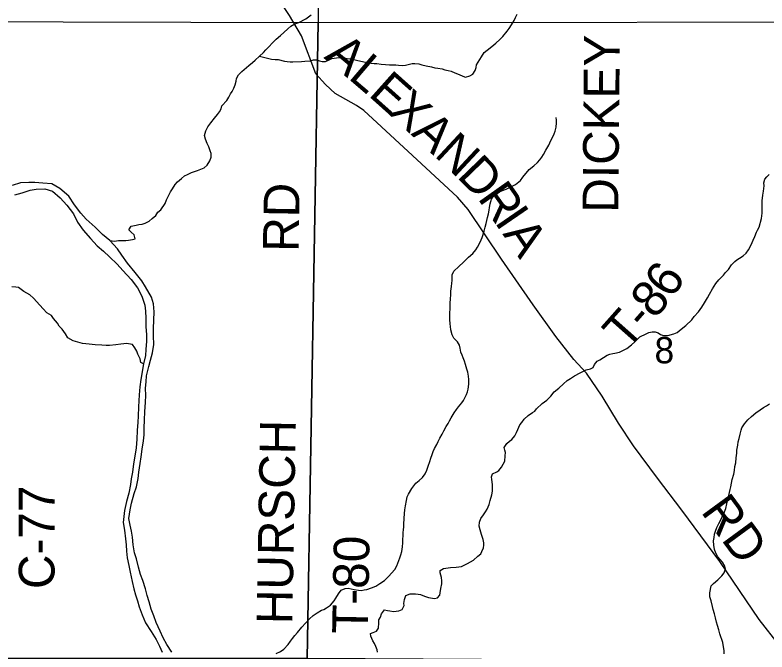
# Model space of a CAD drawing. Extents: x 0 to 34, y 0 to 22.
# Drawn here: x 2.685 to 3.881, y 19.157 to 20.171 of the extents above; entities that cross this region are included whole.
import ezdxf

# ---------------------------------------------------------------- set-up
doc = ezdxf.new("R2010")
doc.units = 0
for name, color, linetype in [('GM_X_Corporation', 7, 'Continuous'), ('GM_X_County_Road', 7, 'Continuous'), ('GM_X_County_Road_Text', 7, 'Continuous'), ('GM_X_Minor_River', 7, 'Continuous'), ('GM_X_Section_Text', 7, 'Continuous'), ('GM_X_Township_Road_Text', 7, 'Continuous')]:
    doc.layers.add(name, color=color, linetype=linetype)

msp = doc.modelspace()

# ---------------------------------------------------------------- linework, layer by layer
at = {"layer": 'GM_X_Corporation'}
for points in [[(4.1833, 20.898), (3.1749, 20.898), (3.1676, 20.1592), (4.1816, 20.1598)], [(3.1676, 20.1592), (3.1497, 19.1471), (2.1459, 19.1467), (2.1533, 20.1617)], [(3.1676, 20.1592), (4.1816, 20.1598), (4.1654, 19.1412), (3.1497, 19.1471)]]:
    msp.add_lwpolyline(points, close=True, dxfattribs=at)
at = {"layer": 'GM_X_County_Road'}
msp.add_lwpolyline([(3.901, 19.1674), (3.8689, 19.2091), (3.8059, 19.3011), (3.7455, 19.3827), (3.7071, 19.4339), (3.6691, 19.4851), (3.6451, 19.5215), (3.6192, 19.5642), (3.594, 19.6011), (3.5739, 19.6226), (3.5452, 19.6595), (3.5095, 19.7098), (3.4591, 19.7826), (3.4058, 19.8616), (3.389, 19.881), (3.3176, 19.9472), (3.2399, 20.0189), (3.2283, 20.0268), (3.1945, 20.0462), (3.1789, 20.0605), (3.1639, 20.0775), (3.1411, 20.1379), (3.122, 20.1703), (3.0912, 20.2166)], dxfattribs=at)
at = {"layer": 'GM_X_Minor_River'}
for points in [[(2.836, 19.812), (2.8435, 19.8112), (2.8496, 19.8123), (2.8568, 19.8118), (2.8617, 19.8118), (2.8659, 19.8125), (2.8719, 19.8136), (2.8765, 19.8147), (2.875, 19.8208), (2.8701, 19.8254), (2.866, 19.8288), (2.8702, 19.8349), (2.8781, 19.8367), (2.8823, 19.8374), (2.8876, 19.8381), (2.8921, 19.8396), (2.8986, 19.8429), (2.9035, 19.8471), (2.9093, 19.852), (2.9123, 19.8572), (2.9169, 19.8606), (2.9238, 19.8708), (2.9264, 19.8765), (2.9303, 19.8852), (2.9326, 19.8893), (2.9357, 19.8942), (2.9399, 19.901), (2.9437, 19.9052), (2.9501, 19.9108), (2.9547, 19.9149), (2.9596, 19.9172), (2.9661, 19.9205), (2.9752, 19.9235), (2.9805, 19.9253), (2.9862, 19.9279), (2.9908, 19.9317), (2.9953, 19.9388), (2.9973, 19.9445), (2.9973, 19.9506), (2.9958, 19.9548), (2.9936, 19.9609), (2.991, 19.9666), (2.9884, 19.9734), (2.9866, 19.9791), (2.9885, 19.9863), (2.992, 19.9931), (2.9965, 19.9995), (3.0023, 20.0067), (3.0072, 20.0127), (3.0103, 20.0169), (3.0133, 20.0214), (3.0141, 20.0263), (3.0221, 20.035), (3.0252, 20.0399), (3.0279, 20.0452), (3.0306, 20.0493), (3.0332, 20.0542), (3.0356, 20.0599), (3.0371, 20.0656), (3.0375, 20.0698), (3.0406, 20.0758), (3.0459, 20.0811), (3.0573, 20.0905), (3.063, 20.0953), (3.0672, 20.0991), (3.0741, 20.1055), (3.0802, 20.1111), (3.084, 20.1153), (3.0886, 20.1198), (3.0954, 20.1269), (3.1007, 20.1322), (3.1072, 20.1382), (3.1125, 20.1431), (3.119, 20.1491), (3.124, 20.1532), (3.13, 20.1566), (3.1365, 20.1592), (3.1479, 20.1648), (3.1521, 20.1678), (3.1562, 20.1712)], [(3.0741, 20.1055), (3.0933, 20.1004), (3.099, 20.1003), (3.1039, 20.0999), (3.1137, 20.0975), (3.1183, 20.0967), (3.1228, 20.0963), (3.1273, 20.0963), (3.141, 20.0969), (3.1463, 20.0976), (3.1546, 20.0979), (3.1599, 20.0994), (3.1652, 20.0997), (3.1697, 20.0982), (3.1739, 20.097), (3.1791, 20.0969), (3.1848, 20.0995), (3.189, 20.1014), (3.1966, 20.1025), (3.2007, 20.1032), (3.2064, 20.1031), (3.2136, 20.1019), (3.2185, 20.1011), (3.2242, 20.1003), (3.2283, 20.0991), (3.2351, 20.0972), (3.2427, 20.0956), (3.2472, 20.0948), (3.2517, 20.0944), (3.2563, 20.0936), (3.2604, 20.0935), (3.2676, 20.0927), (3.2744, 20.0923), (3.2808, 20.0918), (3.2858, 20.0918), (3.2907, 20.0914), (3.2952, 20.0909), (3.3016, 20.0905), (3.3062, 20.0912), (3.3168, 20.0938), (3.3209, 20.0937), (3.3274, 20.0933), (3.3323, 20.0917), (3.3391, 20.0902), (3.3477, 20.0882), (3.3527, 20.087), (3.3579, 20.0862), (3.3647, 20.085), (3.3689, 20.0838), (3.3742, 20.0826), (3.3791, 20.0815), (3.3847, 20.0791), (3.3915, 20.076), (3.3972, 20.0733), (3.4017, 20.0721), (3.4085, 20.074), (3.4135, 20.0766), (3.4169, 20.0826), (3.4188, 20.0875), (3.4192, 20.0917), (3.4246, 20.1), (3.4269, 20.1042), (3.4315, 20.111), (3.4361, 20.1151), (3.4433, 20.1207), (3.4501, 20.1263), (3.4562, 20.132), (3.4608, 20.1365), (3.4677, 20.1452), (3.4711, 20.1493), (3.4749, 20.155), (3.4791, 20.1621), (3.4814, 20.1667), (3.4837, 20.172)], [(3.3739, 19.5207), (3.3762, 19.5252), (3.3789, 19.5297), (3.3838, 19.5376), (3.3876, 19.5429), (3.3907, 19.5471), (3.3957, 19.5535), (3.3983, 19.5576), (3.401, 19.5625), (3.4033, 19.5671), (3.4049, 19.5712), (3.406, 19.5754), (3.4068, 19.5833), (3.4069, 19.5906), (3.4066, 19.5962), (3.4055, 19.6023), (3.404, 19.6073), (3.4018, 19.6145), (3.3999, 19.6202), (3.3977, 19.6252), (3.3962, 19.6297), (3.394, 19.6343), (3.3933, 19.6408), (3.3922, 19.6457), (3.3888, 19.6507), (3.3832, 19.6568), (3.3806, 19.6621), (3.3784, 19.6697), (3.3776, 19.675), (3.3773, 19.6792), (3.377, 19.6864), (3.377, 19.6906), (3.377, 19.6971), (3.3775, 19.7031), (3.3775, 19.7122), (3.378, 19.7194), (3.3784, 19.7255), (3.3784, 19.7316), (3.3796, 19.7388), (3.38, 19.7441), (3.3804, 19.7483), (3.3805, 19.7574), (3.3832, 19.7634), (3.3912, 19.7709), (3.3984, 19.7773), (3.4022, 19.7814), (3.4064, 19.7856), (3.4133, 19.7912), (3.4182, 19.7972), (3.4209, 19.8014), (3.4248, 19.8093), (3.4282, 19.8169), (3.4313, 19.8267), (3.4329, 19.8332), (3.4344, 19.8392), (3.4356, 19.8441), (3.4368, 19.8487), (3.4383, 19.8544), (3.4395, 19.8604), (3.4399, 19.8646), (3.4411, 19.8706), (3.443, 19.8778), (3.4468, 19.8831), (3.4556, 19.8895), (3.4605, 19.8917), (3.4662, 19.8939), (3.4708, 19.8958), (3.4757, 19.8984), (3.4814, 19.901), (3.489, 19.9074), (3.4928, 19.9127), (3.5031, 19.9251), (3.5103, 19.9307), (3.5161, 19.936), (3.5199, 19.9405), (3.5229, 19.9447), (3.5256, 19.9488), (3.5294, 19.9556), (3.534, 19.9639), (3.5375, 19.9711), (3.5406, 19.9771), (3.5425, 19.9817), (3.544, 19.9858), (3.546, 19.9926), (3.5464, 19.9991), (3.5464, 20.0036), (3.5457, 20.0078)], [(3.8559, 19.8049), (3.8592, 19.8124), (3.862, 19.8184), (3.8645, 19.8252), (3.8661, 19.8285), (3.8689, 19.8334), (3.8726, 19.8469), (3.8732, 19.8553), (3.8735, 19.8655), (3.8732, 19.8689), (3.8734, 19.8758), (3.8739, 19.8795), (3.8744, 19.8841), (3.8757, 19.8905), (3.8767, 19.8988), (3.876, 19.9038), (3.8777, 19.9094), (3.8809, 19.9135), (3.8848, 19.9172)], [(2.9056, 19.7114), (2.9024, 19.7221), (2.8929, 19.7383), (2.887, 19.7479), (2.8763, 19.7611), (2.8644, 19.7761), (2.8552, 19.7888), (2.8482, 19.7989), (2.836, 19.812), (2.8244, 19.8214), (2.8125, 19.833), (2.7983, 19.8459), (2.7898, 19.8555), (2.7798, 19.8687), (2.7706, 19.8825), (2.7565, 19.895), (2.7437, 19.9021), (2.7293, 19.9035), (2.7168, 19.9041), (2.7074, 19.9043), (2.6941, 19.9038), (2.6807, 19.8995)], [(2.685, 19.8846), (2.6968, 19.8878), (2.7094, 19.8921), (2.7189, 19.8938), (2.7326, 19.8943), (2.745, 19.8907), (2.7569, 19.8801), (2.7677, 19.8685), (2.778, 19.8543), (2.7846, 19.8412), (2.7934, 19.8285), (2.8053, 19.8153), (2.8161, 19.8037), (2.8258, 19.7951), (2.8354, 19.7862), (2.8477, 19.7745), (2.8566, 19.7645), (2.87, 19.7501), (2.88, 19.7366)], [(3.4309, 19.3308), (3.4295, 19.3362), (3.4271, 19.3442), (3.425, 19.3518), (3.4236, 19.3576), (3.4241, 19.3636), (3.4258, 19.3697), (3.4302, 19.3756), (3.4337, 19.3804), (3.4361, 19.3846), (3.4393, 19.392), (3.441, 19.3985), (3.4435, 19.4071), (3.4445, 19.4132), (3.4447, 19.4238), (3.4438, 19.4318), (3.4432, 19.436), (3.4448, 19.4405), (3.4514, 19.4441), (3.4548, 19.4459), (3.4588, 19.4515), (3.4643, 19.4608), (3.4646, 19.4695), (3.4651, 19.4748), (3.464, 19.4783), (3.463, 19.4825), (3.4674, 19.4892), (3.4716, 19.4925), (3.4755, 19.4954), (3.4799, 19.501), (3.483, 19.5066), (3.4847, 19.5115), (3.4867, 19.5152), (3.4879, 19.5186), (3.4914, 19.5223), (3.495, 19.5279), (3.5012, 19.5334), (3.5082, 19.5381), (3.5121, 19.5403), (3.5148, 19.544), (3.5238, 19.5525), (3.5312, 19.558), (3.5374, 19.5643), (3.5429, 19.5713), (3.5499, 19.5772), (3.5577, 19.5838), (3.5632, 19.589), (3.5686, 19.5927), (3.5752, 19.5967), (3.584, 19.6017), (3.5937, 19.606), (3.6005, 19.6077), (3.6048, 19.6099), (3.6068, 19.6148), (3.6108, 19.62), (3.6154, 19.6221), (3.6212, 19.6261), (3.627, 19.6294), (3.6312, 19.6312), (3.6358, 19.6322), (3.6392, 19.6328), (3.6465, 19.6345), (3.6507, 19.6363), (3.6584, 19.6403), (3.6654, 19.6458), (3.6709, 19.651), (3.6748, 19.6543), (3.6791, 19.6587), (3.6891, 19.6634), (3.6933, 19.6655), (3.6987, 19.6669), (3.7032, 19.6668), (3.7081, 19.6651), (3.7119, 19.6627), (3.7164, 19.6607), (3.7236, 19.6609), (3.7328, 19.6633), (3.7382, 19.6658), (3.7448, 19.6709), (3.7522, 19.6768), (3.7616, 19.686), (3.7655, 19.6909), (3.7722, 19.6987), (3.7773, 19.7057), (3.7817, 19.7128), (3.7864, 19.721), (3.7896, 19.7266), (3.7944, 19.7349), (3.8, 19.7438), (3.8043, 19.7494), (3.8117, 19.7568), (3.8149, 19.7612), (3.8199, 19.766), (3.8247, 19.7731), (3.8298, 19.7787), (3.8333, 19.7812), (3.8375, 19.7838), (3.8433, 19.7874), (3.848, 19.7918), (3.8519, 19.7974), (3.8559, 19.8049)], [(2.8896, 19.6159), (2.8856, 19.6181), (2.8841, 19.6238), (2.8808, 19.631), (2.8789, 19.636), (2.876, 19.6413), (2.8722, 19.6466), (2.8624, 19.6479), (2.8582, 19.6475), (2.8533, 19.6472), (2.8454, 19.6461), (2.8355, 19.6447), (2.8302, 19.6451), (2.8234, 19.6456), (2.8125, 19.646), (2.8034, 19.6469), (2.7928, 19.6481), (2.7853, 19.6505), (2.7777, 19.6524), (2.7694, 19.6574), (2.7653, 19.6635), (2.7601, 19.6708), (2.7556, 19.6758), (2.753, 19.6804), (2.7462, 19.688), (2.7432, 19.6926), (2.7361, 19.6972), (2.7301, 19.7033), (2.7248, 19.7094), (2.7147, 19.7202), (2.7087, 19.7255), (2.6993, 19.7309), (2.691, 19.7371), (2.6868, 19.7379), (2.6804, 19.7383)], [(2.88, 19.7366), (2.8869, 19.7232), (2.8915, 19.709), (2.8929, 19.6995), (2.8934, 19.6885), (2.8935, 19.6751), (2.8944, 19.6618), (2.8945, 19.6519), (2.8935, 19.6386), (2.8926, 19.6288), (2.8896, 19.6159), (2.8853, 19.5909), (2.8836, 19.5791), (2.8826, 19.5662), (2.8824, 19.5567), (2.8818, 19.5472), (2.8811, 19.5324), (2.8805, 19.5229), (2.8795, 19.5096), (2.8789, 19.4959), (2.8778, 19.4823), (2.8757, 19.469), (2.8739, 19.4565), (2.8721, 19.4432), (2.87, 19.433), (2.8687, 19.4235), (2.8661, 19.4099), (2.8624, 19.3966), (2.8595, 19.3822), (2.8582, 19.3727), (2.8572, 19.3633), (2.8592, 19.351), (2.8609, 19.3373), (2.8622, 19.3278), (2.8623, 19.3175), (2.8637, 19.3069), (2.8664, 19.295), (2.8685, 19.2843), (2.8716, 19.2694), (2.8744, 19.258), (2.8769, 19.248), (2.8801, 19.2385), (2.8829, 19.2289), (2.8876, 19.2163), (2.893, 19.2036), (2.9019, 19.1901), (2.9096, 19.1771), (2.915, 19.1667), (2.9194, 19.1571)], [(2.9346, 19.1568), (2.9265, 19.1691), (2.9206, 19.1799), (2.9159, 19.1906), (2.9097, 19.2041), (2.9062, 19.2148), (2.9018, 19.2255), (2.8986, 19.237), (2.8954, 19.2473), (2.8926, 19.258), (2.8883, 19.271), (2.8847, 19.2806), (2.8816, 19.2924), (2.8784, 19.3054), (2.8752, 19.315), (2.8732, 19.3276), (2.8723, 19.3401), (2.8706, 19.3497), (2.8685, 19.3592), (2.8664, 19.3699), (2.8686, 19.3832), (2.8707, 19.3938), (2.8748, 19.4097), (2.8785, 19.4203), (2.881, 19.4331), (2.882, 19.4434), (2.8841, 19.457), (2.8859, 19.468), (2.8876, 19.4802), (2.8898, 19.4931), (2.8904, 19.5029), (2.8906, 19.5136), (2.8912, 19.5269), (2.8919, 19.5394), (2.893, 19.555), (2.8932, 19.5652), (2.893, 19.577), (2.8936, 19.5873), (2.8942, 19.5968), (2.8979, 19.6115), (2.9008, 19.6214), (2.904, 19.6331), (2.9058, 19.6464), (2.9053, 19.6601), (2.9056, 19.6722), (2.9062, 19.6855), (2.9065, 19.6985), (2.9056, 19.7114)], [(3.8565, 19.5322), (3.8633, 19.5378), (3.8702, 19.5427), (3.8755, 19.5461), (3.8801, 19.5491), (3.885, 19.552)], [(3.8129, 19.1544), (3.8129, 19.1597), (3.8122, 19.1654), (3.8108, 19.1722), (3.8063, 19.1859), (3.8045, 19.1924), (3.8026, 19.1992), (3.8008, 19.2049), (3.7993, 19.2114), (3.7975, 19.2179), (3.7956, 19.2247), (3.7945, 19.2296), (3.7923, 19.2388), (3.7901, 19.2452), (3.7902, 19.2513), (3.7925, 19.2623), (3.7959, 19.2664), (3.8028, 19.2721), (3.8093, 19.2784), (3.8131, 19.2833), (3.8154, 19.2898), (3.8139, 19.294), (3.8106, 19.3004), (3.8031, 19.3089), (3.7997, 19.3146), (3.7975, 19.3203), (3.7964, 19.3271), (3.7961, 19.334), (3.7969, 19.3396), (3.7976, 19.3446), (3.7992, 19.3495), (3.8015, 19.3555), (3.8046, 19.3616), (3.8073, 19.3665), (3.81, 19.3725), (3.8134, 19.3801), (3.8157, 19.3857), (3.8173, 19.3929), (3.8189, 19.4013), (3.8204, 19.4062), (3.8216, 19.4111), (3.8227, 19.416), (3.8235, 19.4202), (3.8259, 19.4316), (3.8282, 19.4403), (3.8294, 19.4459), (3.8302, 19.4524), (3.8314, 19.4581), (3.8322, 19.466), (3.833, 19.4736), (3.8334, 19.4785), (3.8346, 19.4861), (3.8354, 19.4914), (3.837, 19.4971), (3.8385, 19.5039), (3.8401, 19.51), (3.8412, 19.5141), (3.8451, 19.5205), (3.8504, 19.5266), (3.8565, 19.5322)], [(3.1008, 19.1548), (3.1073, 19.1578), (3.113, 19.1615), (3.1194, 19.169), (3.1233, 19.1743), (3.1267, 19.1785), (3.1305, 19.1834), (3.1347, 19.1883), (3.1416, 19.1965), (3.1473, 19.2029), (3.1538, 19.2101), (3.1595, 19.2153), (3.1656, 19.2198), (3.1724, 19.2236), (3.1766, 19.225), (3.1808, 19.2273), (3.1868, 19.2318), (3.1929, 19.2386), (3.1956, 19.2431), (3.1995, 19.2499), (3.204, 19.2555), (3.2101, 19.2585), (3.215, 19.2588), (3.2196, 19.258), (3.2248, 19.2565), (3.2316, 19.2557), (3.2358, 19.2552), (3.2403, 19.2559), (3.2445, 19.2567), (3.2521, 19.2593), (3.2589, 19.2622), (3.2654, 19.2663), (3.2726, 19.2712), (3.2794, 19.2772), (3.2894, 19.2885), (3.2924, 19.2945), (3.2959, 19.3029), (3.2974, 19.307), (3.299, 19.3119), (3.3005, 19.3172), (3.3013, 19.3244), (3.3018, 19.3309), (3.3022, 19.3369), (3.3026, 19.3423), (3.3026, 19.3476), (3.3031, 19.3517), (3.3035, 19.3563), (3.3035, 19.3608), (3.3043, 19.3699), (3.3048, 19.3775), (3.3052, 19.3836), (3.306, 19.3896), (3.3076, 19.3984), (3.3087, 19.4044), (3.311, 19.4086), (3.3164, 19.4176), (3.3195, 19.4218), (3.3229, 19.4259), (3.3278, 19.43), (3.3332, 19.4349), (3.3374, 19.4406), (3.3401, 19.4466), (3.3424, 19.453), (3.3447, 19.4606), (3.3466, 19.4659), (3.3486, 19.4716), (3.3501, 19.4765), (3.3524, 19.481), (3.3559, 19.4874), (3.3582, 19.4924), (3.3608, 19.4976), (3.3643, 19.5037), (3.3674, 19.5093), (3.3708, 19.5158), (3.3739, 19.5207)], [(3.2617, 19.1571), (3.2614, 19.1609), (3.2592, 19.1659), (3.2567, 19.1709), (3.2545, 19.1752), (3.2509, 19.1825), (3.2507, 19.1866), (3.2549, 19.188), (3.2603, 19.1902), (3.2634, 19.1954), (3.2636, 19.2034), (3.2641, 19.2083), (3.2665, 19.2124), (3.2682, 19.218), (3.2726, 19.2244), (3.2775, 19.2235), (3.2813, 19.2226), (3.2873, 19.2217), (3.2957, 19.2226), (3.3011, 19.2247), (3.3039, 19.2311), (3.3036, 19.2345), (3.3049, 19.2405), (3.307, 19.2473), (3.3139, 19.2498), (3.3223, 19.2496), (3.3264, 19.2491), (3.3299, 19.2486), (3.334, 19.247), (3.3381, 19.2453), (3.343, 19.2437), (3.3491, 19.2428), (3.3525, 19.2423), (3.3571, 19.2433), (3.3606, 19.2478), (3.3615, 19.2515), (3.3624, 19.2583), (3.3638, 19.2655), (3.3639, 19.2704), (3.3633, 19.2758), (3.3622, 19.2796), (3.3616, 19.2834), (3.3613, 19.2868), (3.3667, 19.2901), (3.3778, 19.2917), (3.3869, 19.2922), (3.3953, 19.2935), (3.4049, 19.2978), (3.4146, 19.3032), (3.4212, 19.3095), (3.4259, 19.3135), (3.4279, 19.3172), (3.4303, 19.3232), (3.4308, 19.3274), (3.4309, 19.3308)]]:
    msp.add_lwpolyline(points, dxfattribs=at)

# ---------------------------------------------------------------- texts
at = {"layer": 'GM_X_County_Road_Text'}
for s, height, rotation, p in [('A', 0.0568, 319.8962, (3.1754, 20.1028)), ('L', 0.0568, 319.4652, (3.2136, 20.0707)), ('E', 0.0568, 318.2458, (3.2457, 20.0433)), ('X', 0.0568, 317.2571, (3.2772, 20.0151)), ('A', 0.0568, 317.1539, (3.3139, 19.9812)), ('N', 0.0568, 317.0804, (3.3505, 19.9472)), ('D', 0.0568, 314.0327, (3.3866, 19.9137)), ('R', 0.0568, 305.385, (3.4199, 19.8795)), ('I', 0.0568, 304.4619, (3.4468, 19.8417)), ('A', 0.0568, 304.4241, (3.46, 19.8225)), ('C-77', 0.05682, 90, (2.7481, 19.2574)), ('RD', 0.05682, 306.2788, (3.7748, 19.3807))]:
    msp.add_text(s, height=height, rotation=rotation, dxfattribs=at).set_placement(p)
at = {"layer": 'GM_X_Section_Text'}
msp.add_text('8', height=0.0419, rotation=0, dxfattribs=at).set_placement((3.7023, 19.6166))
at = {"layer": 'GM_X_Township_Road_Text'}
for s, height, rotation, p in [('DICKEY', 0.05682, 89.4578, (3.6445, 19.8561)), ('RD', 0.05682, 89.0118, (3.1362, 19.7936)), ('6', 0.0568, 55.8642, (3.7294, 19.7176)), ('8', 0.0568, 49.4826, (3.7025, 19.6855)), ('T', 0.0568, 48.4674, (3.6582, 19.6353)), ('-', 0.0568, 48.6533, (3.6865, 19.6673)), ('HURSCH', 0.05682, 88.9829, (3.1262, 19.2011)), ('T-80', 0.05682, 88.9397, (3.2463, 19.1856))]:
    msp.add_text(s, height=height, rotation=rotation, dxfattribs=at).set_placement(p)

doc.saveas('drawing.dxf')
